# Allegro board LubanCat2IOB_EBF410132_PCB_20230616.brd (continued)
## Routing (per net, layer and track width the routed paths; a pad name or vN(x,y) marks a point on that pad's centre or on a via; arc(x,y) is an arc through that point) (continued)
MIPI_DSI_TX1_D0P: length 207.4
  TOP w0.124: v1(116.97,56.97) 117.27,57.27 130.78,57.27 133.78,54.28 150.55,54.28 150.64,54.19 J26.26 ; v1(19.89,66.73) 20.19,67.03 35.7,67.03 35.87,66.86 35.87,64.72 35.78,64.63 J3.15
  ART03 w0.113: v1(19.89,66.73) 20.21,67.05 20.43,67.05 20.62,66.86 20.62,48.34 21.03,47.94 21.4,47.94 arc(21.46,47.91) 21.48,47.86 arc(21.5,47.8) 21.56,47.77 21.85,47.77 arc(21.91,47.8) 21.93,47.86 arc(21.95,47.91) 22.01,47.94 22.3,47.94 arc(22.36,47.91) 22.38,47.86 arc(22.41,47.8) 22.46,47.77 22.75,47.77 arc(22.81,47.8) 22.83,47.86 arc(22.86,47.91) 22.91,47.94 23.2,47.94 arc(23.26,47.91) 23.28,47.86 arc(23.31,47.8) 23.36,47.77 23.65,47.77 arc(23.71,47.8) 23.73,47.86 arc(23.76,47.91) 23.82,47.94 32.68,47.94 32.97,48.23 32.97,49.64 33.11,49.77 33.29,49.77 33.42,49.64 33.42,48.28 33.77,47.94 34.22,47.94 34.51,48.23 34.51,49.64 34.64,49.77 34.83,49.77 34.96,49.64 34.96,48.28 35.3,47.94 35.75,47.94 36.04,48.23 36.04,49.64 36.17,49.77 36.36,49.77 36.49,49.64 36.49,48.28 36.84,47.94 37.28,47.94 37.58,48.23 37.58,49.64 37.71,49.77 37.9,49.77 38.03,49.64 38.03,48.28 38.37,47.94 38.82,47.94 39.11,48.23 39.11,49.64 39.24,49.77 39.43,49.77 39.56,49.64 39.56,48.28 39.9,47.94 40.35,47.94 40.64,48.23 40.64,49.64 40.78,49.77 40.96,49.77 41.1,49.64 41.1,48.28 41.44,47.94 41.89,47.94 42.18,48.23 42.18,49.64 42.31,49.77 42.5,49.77 42.63,49.64 42.63,48.28 42.97,47.94 43.42,47.94 45.99,45.37 92.43,45.37 93.1,44.7 108.41,44.7 108.71,45 108.71,50.29 108.99,50.57 110.5,50.57 110.79,50.87 110.79,57.02 111.05,57.28 116.66,57.28 v1(116.97,56.97)
MIPI_DSI_TX1_D1N: length 208.5
  TOP w0.124: v1(116.99,55.14) 117.25,54.88 129.68,54.88 132.95,51.61 150.55,51.61 150.64,51.69 J26.21 ; J3.21 37.28,64.63 37.2,64.72 37.2,67.91 36.36,68.75 16.71,68.75 v1(16.41,69.05)
  ART03 w0.113: v1(116.99,55.14) 116.69,54.84 115.15,54.84 114.81,54.49 114.81,53.32 115.13,53 116.24,53 116.37,52.87 116.37,52.69 116.24,52.55 115.13,52.55 114.81,52.24 114.81,51.79 115.13,51.47 116.24,51.47 116.37,51.34 116.37,51.15 116.24,51.02 115.13,51.02 114.81,50.7 114.81,50.25 115.13,49.94 116.24,49.94 116.37,49.8 116.37,49.62 116.24,49.48 115.13,49.48 114.81,49.17 114.81,48.72 115.13,48.4 116.24,48.4 116.37,48.27 116.37,48.08 116.24,47.95 115.13,47.95 114.81,47.63 114.81,47 114.59,46.78 111.77,46.78 111.35,46.37 111.35,43.05 110.98,42.68 90.94,42.68 90.17,43.45 44.64,43.45 42.75,45.34 17.86,45.34 17.66,45.53 17.66,68.38 17.3,68.74 16.72,68.74 v1(16.41,69.05)
MIPI_DSI_TX1_D1P: length 208.5
  TOP w0.124: v1(16.41,68.12) 16.71,68.42 36.22,68.42 36.87,67.77 36.87,64.72 36.78,64.63 J3.19 ; v1(116.99,54.22) 117.33,54.56 129.54,54.56 132.82,51.28 150.55,51.28 150.64,51.19 J26.20
  ART03 w0.113: v1(116.99,54.22) 116.69,54.52 115.28,54.52 115.12,54.36 115.12,53.45 115.26,53.32 116.37,53.32 116.69,53 116.69,52.55 116.37,52.24 115.26,52.24 115.12,52.1 115.12,51.92 115.26,51.79 116.37,51.79 116.69,51.47 116.69,51.02 116.37,50.7 115.26,50.7 115.12,50.57 115.12,50.38 115.26,50.25 116.37,50.25 116.69,49.93 116.69,49.49 116.37,49.17 115.26,49.17 115.12,49.04 115.12,48.85 115.26,48.72 116.37,48.72 116.69,48.4 116.69,47.95 116.37,47.63 115.26,47.63 115.12,47.5 115.12,46.87 114.72,46.47 114.09,46.47 arc(114.02,46.44) 114,46.37 arc(113.97,46.3) 113.9,46.27 113.64,46.27 arc(113.57,46.3) 113.54,46.37 arc(113.52,46.44) 113.45,46.47 113.19,46.47 arc(113.12,46.44) 113.09,46.37 arc(113.07,46.3) 113,46.27 112.74,46.27 arc(112.67,46.3) 112.64,46.37 arc(112.61,46.44) 112.55,46.47 111.9,46.47 111.67,46.24 111.67,42.92 111.11,42.36 90.8,42.36 90.04,43.13 44.51,43.13 42.62,45.02 17.72,45.02 17.35,45.4 17.35,68.25 17.17,68.42 16.71,68.42 v1(16.41,68.12)
MIPI_DSI_TX1_D2N: length 208.1
  TOP w0.124: J3.33 40.28,64.63 40.2,64.72 40.2,68.59 37.24,71.54 14.83,71.54 v1(14.5,71.87) ; J26.18 150.64,50.19 150.55,50.11 132.26,50.11 128.84,53.53 120.12,53.53 v1(119.86,53.79)
  ART03 w0.113: v1(14.5,71.87) 14.78,71.59 15.29,71.59 15.63,71.25 15.63,66.86 16.23,66.26 16.23,44.5 16.43,44.3 42.08,44.3 44.09,42.29 88.66,42.29 89.27,41.68 113.93,41.68 117.79,45.54 117.79,53.15 118.15,53.5 119.58,53.5 v1(119.86,53.79)
MIPI_DSI_TX1_D2P: length 208
  TOP w0.124: J26.17 150.64,49.69 150.55,49.78 132.13,49.78 128.7,53.2 120.17,53.2 v1(119.86,52.9) ; v1(14.5,70.94) 14.78,71.22 37.11,71.22 39.87,68.46 39.87,64.72 39.78,64.63 J3.31
  ART03 w0.113: v1(119.86,52.9) 119.58,53.18 118.28,53.18 118.11,53.02 118.11,52.62 arc(118.14,52.55) 118.21,52.52 arc(118.28,52.49) 118.31,52.42 118.31,52.17 arc(118.28,52.1) 118.21,52.07 arc(118.14,52.04) 118.11,51.97 118.11,51.72 arc(118.14,51.65) 118.21,51.62 arc(118.28,51.59) 118.31,51.52 118.31,51.27 arc(118.28,51.2) 118.21,51.17 arc(118.14,51.14) 118.11,51.07 118.11,45.41 114.06,41.37 89.14,41.37 88.53,41.98 43.96,41.98 41.95,43.98 16.3,43.98 15.91,44.37 15.91,66.13 15.32,66.73 15.32,71.12 15.16,71.27 14.83,71.27 v1(14.5,70.94)
MIPI_DSI_TX1_D3N: length 206.9
  TOP w0.124: v1(24.04,73.21) 24.36,72.89 37.87,72.89 41.2,69.57 41.2,64.72 41.28,64.63 J3.37 ; v1(117.86,60.83) 117.63,60.6 117.63,59.05 117.8,58.88 131.14,58.88 133.91,56.11 150.55,56.11 150.64,56.19 J26.30
  ART03 w0.113: v1(24.04,73.21) 23.8,72.96 22.41,72.96 22,72.55 22,51.49 22.4,51.09 30.72,51.09 31.04,51.41 31.04,52.02 31.17,52.16 31.36,52.16 31.49,52.02 31.49,51.41 31.8,51.09 32.25,51.09 32.57,51.41 32.57,52.02 32.7,52.16 32.89,52.16 33.02,52.02 33.02,51.41 33.34,51.09 33.79,51.09 34.1,51.41 34.1,52.02 34.24,52.16 34.42,52.16 34.56,52.02 34.56,51.41 34.87,51.09 35.32,51.09 35.64,51.41 35.64,52.02 35.77,52.16 35.96,52.16 36.09,52.02 36.09,51.41 36.41,51.09 36.86,51.09 37.17,51.41 37.17,52.02 37.31,52.16 37.49,52.16 37.62,52.02 37.62,51.41 37.94,51.09 38.39,51.09 38.71,51.41 38.71,52.02 38.84,52.16 39.03,52.16 39.16,52.02 39.16,51.41 39.48,51.09 45.17,51.09 45.4,50.86 45.4,48.07 46.82,46.66 97.65,46.66 98.18,47.19 98.18,50.77 98.47,51.05 102.08,51.05 102.79,51.76 102.79,58.17 103.31,58.68 117.13,58.68 117.57,59.12 117.57,60.54 v1(117.86,60.83)
MIPI_DSI_TX1_D3P: length 206.9
  TOP w0.124: v1(24.04,72.28) 24.33,72.56 37.74,72.56 40.87,69.43 40.87,64.72 40.78,64.63 J3.35 ; v1(116.97,60.83) 117.3,60.49 117.3,58.92 117.66,58.55 131,58.55 133.78,55.78 150.55,55.78 150.64,55.69 J26.29
  ART03 w0.113: v1(116.97,60.83) 117.25,60.54 117.25,59.25 117,59 103.17,59 102.48,58.3 102.48,51.89 101.95,51.37 98.33,51.37 97.87,50.9 97.87,47.32 97.52,46.97 46.95,46.97 45.72,48.21 45.72,50.99 45.3,51.41 39.61,51.41 39.47,51.54 39.47,52.16 39.16,52.47 38.71,52.47 38.39,52.16 38.39,51.54 38.26,51.41 38.07,51.41 37.94,51.54 37.94,52.16 37.62,52.47 37.17,52.47 36.86,52.16 36.86,51.54 36.73,51.41 36.54,51.41 36.41,51.54 36.41,52.16 36.09,52.47 35.64,52.47 35.32,52.16 35.32,51.54 35.19,51.41 35,51.41 34.87,51.54 34.87,52.16 34.55,52.47 34.11,52.47 33.79,52.16 33.79,51.54 33.66,51.41 33.47,51.41 33.34,51.54 33.34,52.16 33.02,52.47 32.57,52.47 32.25,52.16 32.25,51.54 32.12,51.41 31.94,51.41 31.8,51.54 31.8,52.16 31.49,52.47 31.04,52.47 30.72,52.16 30.72,51.54 30.59,51.41 28.71,51.41 arc(28.65,51.43) 28.62,51.49 arc(28.6,51.56) 28.54,51.58 28.26,51.58 arc(28.2,51.56) 28.17,51.49 arc(28.15,51.43) 28.08,51.41 27.84,51.41 arc(27.76,51.44) 27.73,51.52 arc(27.7,51.6) 27.62,51.63 27.39,51.63 arc(27.31,51.6) 27.28,51.52 arc(27.25,51.44) 27.16,51.41 26.94,51.41 arc(26.86,51.44) 26.83,51.52 arc(26.79,51.6) 26.71,51.63 26.49,51.63 arc(26.41,51.6) 26.38,51.52 arc(26.34,51.44) 26.26,51.41 26.04,51.41 arc(25.96,51.44) 25.93,51.52 arc(25.89,51.6) 25.81,51.63 25.59,51.63 arc(25.51,51.6) 25.47,51.52 arc(25.44,51.44) 25.36,51.41 25.14,51.41 arc(25.06,51.44) 25.02,51.52 arc(24.99,51.6) 24.91,51.63 24.69,51.63 arc(24.61,51.6) 24.57,51.52 arc(24.54,51.44) 24.46,51.41 24.22,51.41 arc(24.15,51.44) 24.12,51.51 arc(24.09,51.58) 24.02,51.61 23.77,51.61 arc(23.7,51.58) 23.67,51.51 arc(23.64,51.44) 23.56,51.41 22.53,51.41 22.31,51.62 22.31,72.42 22.54,72.65 23.8,72.65 24.04,72.41 v1(24.04,72.28)
OE: length 4.4
  TOP w0.156: U21.8 142.43,74.62 142.61,74.45 142.61,72.73 R83.2
ON/OFF_KEY: length 54.5
  TOP w0.156: J1.25 38.28,24.25 38.13,24.41 34.52,24.41 v1(34.04,24.89)
  ART03 w0.142: v1(12.79,23.17) 12.79,19.53 13.08,19.25 33.75,19.25 34.04,19.53 34.04,22.78 33.56,23.26 33.56,24.41 v1(34.04,24.89)
  BOTTOM w0.156: v1(12.79,23.17) C64.1 12.73,22.53 12.73,20.21 D2.2 12.95,18.71 12.95,11.56 13.27,11.25 15.26,11.25 SW2.2
PCIE20_CLKREQN_M1: length 89.5
  TOP w0.156: J4.37 v1(66.28,64.94)
  ART03 w0.142: v1(66.28,64.94) 66.28,53.85 66.57,53.56 92.65,53.56 92.94,53.85 92.94,55.88 94.16,57.1 96.81,57.1 96.95,57.24 96.95,63.62 97.63,64.3 107.97,64.3 108.39,64.72 108.39,71.43 108.92,71.95 124.86,71.95 v1(125.48,72.57)
  BOTTOM w0.156: R30.1 v1(125.48,72.57)
PCIE20_PERSTN_M1: length 60.5
  TOP w0.156: v1(95.09,60.75) 95.6,61.26 97.12,61.26 97.43,61.57 97.43,62.89 97.82,63.27 116.56,63.27 116.97,63.67 R63.2 ; J4.59 v1(71.78,61.94)
  ART03 w0.142: v1(95.09,60.75) 95.57,60.28 95.57,59.23 95.11,58.77 89.67,58.77 89.38,58.49 89.38,56.06 89.1,55.77 72.55,55.77 72.26,56.06 72.26,61.46 v1(71.78,61.94)
PCIE20_REFCLKN: length 142.6
  TOP w0.179: J35.11 124.7,75.42 124.49,75.22 124.49,73.45 124.03,73 117.81,73 v1(117.5,72.69) ; J1.54 45.28,27.72 45.22,27.78 45.22,40.98 49.28,45.03 98.69,45.03 99.14,45.49 99.14,46.1 v1(99.44,46.4)
  BOTTOM w0.179: v1(99.44,46.4) 99.14,46.1 99.14,45.44 98.6,44.9 97.33,44.9 96.7,45.54 96.7,60.25 99.8,63.35 99.8,76.53 100.5,77.24 114.45,77.24 115.47,76.22 118.57,76.22 119.1,75.69 119.1,73.42 118.62,72.94 117.75,72.94 v1(117.5,72.69)
PCIE20_REFCLKP: length 142.6
  TOP w0.179: J35.13 123.9,75.42 124.11,75.22 124.11,73.61 123.88,73.38 117.8,73.38 v1(117.5,73.68) ; J1.52 44.78,27.72 44.84,27.78 44.84,41.14 49.12,45.42 98.53,45.42 98.76,45.64 98.76,46.1 v1(98.46,46.4)
  BOTTOM w0.179: v1(98.46,46.4) 98.76,46.1 98.76,45.6 98.44,45.29 97.49,45.29 97.08,45.7 97.08,60.09 100.18,63.19 100.18,71.87 arc(100.23,71.99) 100.36,72.04 arc(100.48,72.1) 100.53,72.22 100.53,72.58 arc(100.48,72.71) 100.36,72.76 arc(100.23,72.81) 100.18,72.94 100.18,73.3 arc(100.23,73.42) 100.36,73.47 arc(100.48,73.53) 100.53,73.65 100.53,74.01 arc(100.48,74.14) 100.36,74.19 arc(100.23,74.24) 100.18,74.37 100.18,74.72 arc(100.23,74.85) 100.36,74.9 arc(100.48,74.95) 100.53,75.08 100.53,75.44 arc(100.48,75.56) 100.36,75.62 arc(100.23,75.67) 100.18,75.79 100.18,76.37 100.66,76.86 101.38,76.86 arc(101.49,76.81) 101.54,76.69 101.54,76.67 arc(101.59,76.55) 101.71,76.5 102.09,76.5 arc(102.21,76.55) 102.26,76.67 102.26,76.69 arc(102.3,76.81) 102.42,76.86 102.81,76.86 arc(102.92,76.81) 102.97,76.69 102.97,76.67 arc(103.02,76.55) 103.14,76.5 103.52,76.5 arc(103.64,76.55) 103.69,76.67 103.69,76.69 arc(103.73,76.81) 103.85,76.86 104.23,76.86 arc(104.35,76.81) 104.4,76.69 104.4,76.67 arc(104.45,76.55) 104.56,76.5 104.95,76.5 arc(105.07,76.55) 105.11,76.67 105.11,76.69 arc(105.16,76.81) 105.28,76.86 105.66,76.86 arc(105.78,76.81) 105.83,76.69 105.83,76.67 arc(105.88,76.55) 105.99,76.5 106.38,76.5 arc(106.49,76.55) 106.54,76.67 106.54,76.69 arc(106.59,76.81) 106.71,76.86 107.09,76.86 arc(107.21,76.81) 107.26,76.69 107.26,76.67 arc(107.3,76.55) 107.42,76.5 107.81,76.5 arc(107.92,76.55) 107.97,76.67 107.97,76.69 arc(108.02,76.81) 108.14,76.86 111.97,76.86 arc(112.08,76.81) 112.13,76.69 arc(112.18,76.57) 112.29,76.53 112.68,76.53 arc(112.8,76.57) 112.84,76.69 arc(112.89,76.81) 113.01,76.86 114.29,76.86 115.31,75.84 118.42,75.84 118.72,75.54 118.72,73.58 118.47,73.33 117.85,73.33 v1(117.5,73.68)
PCIE20_RXN: length 148.5
  TOP w0.179: v1(100.2,47.34) 99.9,47.65 98.32,47.65 96.97,46.3 48.24,46.3 43.72,41.78 43.72,27.78 43.78,27.72 J1.48 ; v1(105.84,72.49) 106.12,72.21 106.12,71.34 106.55,70.91 108.81,70.91 109.35,71.45 115.93,71.45 116.49,72.01 116.49,75.22 116.7,75.42 J35.23
  BOTTOM w0.179: v1(105.84,72.49) 106.15,72.19 106.15,71.27 105.94,71.07 101.55,71.07 101.07,70.58 101.07,61.73 100.86,61.52 99.67,61.52 99.24,61.09 99.24,60.48 99.67,60.05 101.09,60.05 101.3,59.84 101.3,59.52 101.06,59.28 98.2,59.28 97.76,58.85 97.76,58.24 98.17,57.83 101.21,57.83 101.4,57.64 101.4,57.35 101.16,57.11 98.22,57.11 97.76,56.66 97.76,56.04 98.17,55.64 101.21,55.64 101.4,55.45 101.4,55.16 101.16,54.92 98.22,54.92 97.76,54.46 97.76,53.85 98.17,53.44 100.98,53.44 101.17,53.26 101.17,52.96 100.91,52.7 98.37,52.7 97.79,52.12 97.79,48.07 98.22,47.65 99.9,47.65 v1(100.2,47.34)
PCIE20_RXP: length 148.1
  TOP w0.179: J35.25 115.9,75.42 116.11,75.22 116.11,72.16 115.77,71.83 109.2,71.83 108.65,71.29 106.71,71.29 106.5,71.5 106.5,72.16 v1(106.83,72.49) ; J1.46 43.28,27.72 43.34,27.78 43.34,41.94 48.08,46.68 96.81,46.68 98.17,48.03 99.9,48.03 v1(100.2,48.33)
  BOTTOM w0.179: v1(100.2,48.33) 99.9,48.03 98.37,48.03 98.17,48.23 98.17,51.96 98.53,52.32 101.07,52.32 101.55,52.8 101.55,53.42 101.14,53.83 98.33,53.83 98.15,54.01 98.15,54.31 98.38,54.54 101.32,54.54 101.78,55 101.78,55.61 101.37,56.02 98.33,56.02 98.15,56.2 98.15,56.5 98.38,56.73 101.32,56.73 101.78,57.19 101.78,57.8 101.37,58.21 98.33,58.21 98.15,58.39 98.15,58.69 98.36,58.9 101.22,58.9 101.68,59.36 101.68,59.99 101.24,60.43 99.83,60.43 99.62,60.64 99.62,60.93 99.83,61.14 101.02,61.14 101.45,61.57 101.45,70.42 101.71,70.68 102.04,70.68 arc(102.13,70.65) 102.17,70.56 arc(102.2,70.47) 102.29,70.43 102.75,70.43 arc(102.84,70.47) 102.88,70.56 arc(102.92,70.65) 103.01,70.68 103.47,70.68 arc(103.56,70.65) 103.6,70.56 arc(103.63,70.47) 103.72,70.43 104.18,70.43 arc(104.27,70.47) 104.31,70.56 arc(104.35,70.65) 104.44,70.68 104.9,70.68 arc(104.99,70.65) 105.02,70.56 arc(105.06,70.47) 105.15,70.43 105.61,70.43 arc(105.7,70.47) 105.74,70.56 arc(105.78,70.65) 105.87,70.68 106.1,70.68 106.53,71.11 106.53,72.19 v1(106.83,72.49)
PCIE20_TXN: length 137.8
  TOP w0.179: J1.44 42.78,27.72 42.75,27.75 42.75,43.38 46.97,47.6 96.52,47.6 98.04,49.12 99.92,49.12 100.36,49.55 100.36,49.95 100.38,49.97 100.38,49.99 v1(100.66,50.26)
  BOTTOM w0.179: C53.1 113.27,71.46 113.27,69.24 112.76,68.73 102.95,68.73 102.59,68.37 102.59,65.52 102.8,65.31 104.47,65.31 104.88,64.91 104.88,64.26 104.47,63.86 103.16,63.86 102.92,63.62 102.92,63.33 103.1,63.14 105.28,63.14 105.69,62.74 105.69,62.12 105.23,61.67 103.16,61.67 102.92,61.43 102.92,61.13 103.1,60.95 105.28,60.95 105.69,60.54 105.69,59.93 105.23,59.47 103.16,59.47 102.92,59.24 102.92,58.94 103.1,58.76 105.28,58.76 105.69,58.35 105.69,57.74 105.23,57.28 103.16,57.28 102.92,57.05 102.92,56.75 103.1,56.57 104.85,56.57 105.28,56.13 105.28,55.52 104.85,55.09 103.16,55.09 102.92,54.85 102.92,54.56 103.1,54.37 104.85,54.37 105.28,53.94 105.28,53.33 104.85,52.9 102.83,52.9 102.59,52.66 102.59,51.83 102.09,51.33 100.62,51.33 100.35,51.07 100.35,50.56 v1(100.66,50.26)
PCIE20_TXP: length 137.8
  TOP w0.179: v1(99.67,50.26) 99.97,49.96 99.97,49.71 99.77,49.5 97.89,49.5 96.36,47.98 46.81,47.98 42.37,43.54 42.37,27.65 42.28,27.56 J1.42
  BOTTOM w0.179: C54.1 112.89,71.46 112.89,69.4 112.6,69.11 102.79,69.11 102.21,68.52 102.21,65.36 102.64,64.93 104.32,64.93 104.49,64.75 104.49,64.42 104.32,64.24 103,64.24 102.54,63.78 102.54,63.17 102.95,62.76 105.12,62.76 105.31,62.58 105.31,62.28 105.07,62.05 103,62.05 102.54,61.59 102.54,60.98 102.95,60.57 105.12,60.57 105.31,60.39 105.31,60.09 105.07,59.85 103,59.85 102.54,59.4 102.54,58.78 102.95,58.38 105.12,58.38 105.31,58.19 105.31,57.9 105.07,57.66 103,57.66 102.54,57.2 102.54,56.59 102.95,56.19 104.69,56.19 104.9,55.98 104.9,55.68 104.69,55.47 103,55.47 102.54,55.01 102.54,54.4 102.95,53.99 104.69,53.99 104.9,53.78 104.9,53.49 104.69,53.28 102.67,53.28 102.21,52.82 102.21,51.99 101.93,51.71 100.46,51.71 99.97,51.23 99.97,50.56 v1(99.67,50.26)
PCIE20_WAKEN_M1: length 94.4
  TOP w0.156: v1(66.28,65.94) 66.78,65.44 J4.39
  ART03 w0.142: v1(125.48,71.57) 125.38,71.47 109.12,71.47 108.81,71.17 108.81,64.33 108.36,63.88 97.97,63.88 97.38,63.29 97.38,56.72 97.24,56.57 94.25,56.57 93.4,55.72 93.4,53.41 93.12,53.14 66.09,53.14 65.81,53.42 65.81,65.46 v1(66.28,65.94)
  BOTTOM w0.156: v1(125.48,71.57) 125.91,72.01 126.81,72.01 R29.1
PCIE30_REFCLKN_IN: length 183.3
  TOP w0.179: R78.2 145.03,82.42 145.35,82.73 145.35,83.02 v1(145.08,83.29) ; J1.71 v1(49.78,23.89)
  ART03 w0.163: v1(137.91,47.34) 137.91,47.43 137.7,47.64 137.08,47.64 136.92,47.47 136.92,46.83 137.16,46.59 138.96,46.59 139.41,46.15 139.41,45.55 139,45.15 137.72,45.15 137.53,44.96 137.53,44.69 137.72,44.5 139,44.5 139.41,44.09 139.41,43.52 139,43.11 137.72,43.11 137.53,42.92 137.53,42.65 137.72,42.46 139,42.46 139.41,42.06 139.41,41.49 139,41.08 137.72,41.08 137.53,40.89 137.53,40.59 137.69,40.43 139,40.43 139.41,40.02 139.41,39.39 138.96,38.95 135.25,38.95 135.09,38.79 135.09,37.53 134.69,37.13 134.11,37.13 133.71,37.53 133.71,38.79 133.54,38.95 132.82,38.95 132.64,38.77 132.64,36.52 130.81,34.69 130.81,30.59 130.31,30.1 69.24,30.1 66.43,32.9 51.53,32.9 50.21,31.58 50.21,25.48 50.27,25.42 50.27,24.69 49.78,24.2 v1(49.78,23.89)
  ART04 w0.163: v1(137.91,47.34) 137.64,47.6 136.95,47.6 136.55,48 136.55,51.21 137.04,51.7 146.89,51.7 147.21,52.01 147.21,81.41 147.05,81.57 145.85,81.57 145.36,82.06 145.36,83.01 v1(145.08,83.29)
  BOTTOM w0.179: R78.2 145.36,82.28 145.36,83.01 v1(145.08,83.29)
PCIE30_REFCLKP_IN: length 184
  TOP w0.179: J1.69 49.28,24.39 v1(49.78,24.89) ; R77.2 146.05,82.42 145.73,82.73 145.73,83.02 v1(146.01,83.29)
  ART03 w0.163: v1(137.91,48.31) 137.6,48 136.93,48 136.55,47.62 136.55,46.68 137.01,46.22 138.81,46.22 139.04,46 139.04,45.71 138.85,45.52 137.57,45.52 137.16,45.11 137.16,44.54 137.57,44.13 138.85,44.13 139.04,43.94 139.04,43.67 138.85,43.48 137.57,43.48 137.16,43.08 137.16,42.5 137.57,42.1 138.85,42.1 139.04,41.91 139.04,41.64 138.85,41.45 137.57,41.45 137.16,41.04 137.16,40.44 137.54,40.06 138.85,40.06 139.04,39.87 139.04,39.54 138.81,39.32 135.1,39.32 134.72,38.94 134.72,37.69 134.53,37.5 134.26,37.5 134.07,37.69 134.07,38.94 133.69,39.32 132.66,39.32 132.27,38.92 132.27,36.67 130.44,34.84 130.44,30.75 130.16,30.46 69.39,30.46 66.58,33.27 51.38,33.27 49.84,31.73 49.84,25.51 49.78,25.45 v1(49.78,24.89)
  ART04 w0.163: v1(146.01,83.29) 145.73,83.01 145.73,82.21 146,81.94 147.2,81.94 147.57,81.56 147.57,51.86 147.04,51.33 140.18,51.33 arc(140.07,51.29) 140.03,51.18 arc(139.98,51.07) 139.87,51.02 139.53,51.02 arc(139.42,51.07) 139.37,51.18 arc(139.33,51.29) 139.22,51.33 138.88,51.33 arc(138.77,51.29) 138.72,51.18 arc(138.68,51.07) 138.57,51.02 138.23,51.02 arc(138.12,51.07) 138.07,51.18 arc(138.03,51.29) 137.92,51.33 137.19,51.33 136.92,51.06 136.92,48.15 137.1,47.97 137.57,47.97 v1(137.91,48.31)
  BOTTOM w0.179: v1(146.01,83.29) 145.75,83.03 145.75,82.26 R77.2
PCIE30_RX0N: length 186.1
  TOP w0.179: v1(146.46,94.29) 146.71,94.04 146.71,93.14 146.65,93.08 J17.41 ; J1.61 47.28,24.39 v1(46.78,24.89)
  ART03 w0.163: v1(46.78,24.89) 46.78,25.44 46.84,25.51 46.84,32.07 50.26,35.48 67.82,35.48 70.46,32.85 126.88,32.85 127.12,33.08 127.12,37.32 127.53,37.74 128.58,37.74 v1(128.88,38.04)
  ART04 w0.163: v1(128.88,38.04) 129.18,37.74 133.19,37.74 133.44,37.99 133.44,40.76 133.92,41.25 147.72,41.25 147.89,41.42 147.89,46.2 148.36,46.67 151.6,46.67 151.83,46.9 151.83,82.64 152.97,83.78 152.97,90.91 152.65,91.24 147.86,91.24 146.72,92.38 146.72,94.03 v1(146.46,94.29)
PCIE30_RX0P: length 186.1
  TOP w0.179: J17.43 147.15,93.08 147.09,93.14 147.09,94.04 v1(147.34,94.29) ; J1.59 v1(46.78,23.89)
  ART03 w0.163: v1(128.88,37.07) 128.58,37.37 127.69,37.37 127.48,37.17 127.48,32.93 127.04,32.48 70.31,32.48 67.67,35.12 50.41,35.12 47.21,31.92 47.21,25.51 47.27,25.44 47.27,24.66 46.78,24.17 v1(46.78,23.89)
  ART04 w0.163: v1(147.34,94.29) 147.08,94.03 147.08,92.53 148.01,91.61 152.8,91.61 153.34,91.06 153.34,83.63 152.2,82.49 152.2,46.75 151.75,46.3 148.51,46.3 148.26,46.05 148.26,41.27 147.87,40.88 134.08,40.88 133.81,40.61 133.81,37.84 133.34,37.37 129.18,37.37 v1(128.88,37.07)
PCIE30_RX1N: length 186.1
  TOP w0.179: J1.65 48.28,24.39 v1(47.78,24.89) ; v1(143.46,94.29) 143.71,94.04 143.71,93.14 143.65,93.08 J17.29
  ART03 w0.163: v1(130.25,39.64) 130.56,39.34 130.56,37.06 129.04,35.55 129.04,32.27 128.71,31.93 69.9,31.93 67.17,34.67 50.8,34.67 47.84,31.71 47.84,25.54 47.78,25.48 47.78,24.89 v1(47.78,24.89)
  ART04 w0.163: v1(143.46,94.29) 143.72,94.03 143.72,88.76 144.15,88.33 150.43,88.33 150.87,87.89 150.87,48.93 150.57,48.64 146.07,48.64 145.64,48.22 145.64,43.15 145.34,42.85 144.22,42.85 144.03,43.04 144.03,43.53 143.63,43.94 143.05,43.94 142.65,43.53 142.65,43.04 142.46,42.85 131.08,42.85 130.59,42.36 130.59,39.98 v1(130.25,39.64)
PCIE30_RX1P: length 186.1
  TOP w0.179: v1(144.34,94.29) 144.09,94.04 144.09,93.14 144.15,93.08 J17.31 ; J1.63 v1(47.78,23.89)
  ART03 w0.163: v1(47.78,23.89) 47.78,24.16 48.27,24.65 48.27,25.46 48.21,25.52 48.21,31.56 50.95,34.3 67.01,34.3 69.75,31.57 128.86,31.57 129.41,32.12 129.41,35.4 130.92,36.91 130.92,39.34 v1(131.22,39.64)
  ART04 w0.163: v1(144.34,94.29) 144.08,94.03 144.08,88.91 144.3,88.69 150.58,88.69 151.23,88.04 151.23,48.78 150.72,48.27 146.22,48.27 146.01,48.06 146.01,43 145.49,42.48 144.07,42.48 143.67,42.89 143.67,43.38 143.48,43.57 143.21,43.57 143.01,43.38 143.01,42.89 142.61,42.48 131.23,42.48 130.96,42.21 130.96,39.91 v1(131.22,39.64)
PCIE30_TX0N: length 182.5
  TOP w0.179: J1.53 45.28,24.39 v1(44.78,24.89)
  ART03 w0.163: v1(128.26,41.62) 127.96,41.32 124.83,41.32 124.33,40.82 124.33,34.95 124.05,34.67 71.4,34.67 68.9,37.17 49.13,37.17 44.85,32.89 44.85,25.41 44.78,25.34 v1(44.78,24.89)
  ART04 w0.163: v1(128.26,41.62) 128.56,41.32 128.87,41.32 129.05,41.5 129.05,43.45 129.57,43.96 139.01,43.96 139.38,44.33 139.38,49.63 139.85,50.1 140.83,50.1 141.24,49.69 141.24,48.38 141.43,48.19 141.7,48.19 141.89,48.38 141.89,49.69 142.29,50.1 142.87,50.1 143.27,49.69 143.27,48.38 143.46,48.19 143.73,48.19 143.92,48.38 143.92,49.69 144.33,50.1 147.86,50.1 148.15,50.38 148.15,51.13 148.55,51.54 149.51,51.54 149.7,51.73 149.7,52 149.51,52.19 148.55,52.19 148.15,52.59 148.15,53.17 148.55,53.57 149.51,53.57 149.7,53.76 149.7,54.03 149.51,54.22 148.55,54.22 148.15,54.63 148.15,55.2 148.55,55.6 149.51,55.6 149.7,55.8 149.7,56.07 149.51,56.26 148.55,56.26 148.15,56.66 148.15,86.53 v1(147.89,86.78)
  BOTTOM w0.179: C125.1 148.11,87.66 148.11,86.99 v1(147.89,86.78)
PCIE30_TX0P: length 182.6
  TOP w0.179: J1.51 v1(44.78,23.89)
  ART03 w0.163: v1(44.78,23.89) 44.78,24.2 45.28,24.69 45.28,25.35 45.22,25.41 45.22,32.74 49.28,36.8 68.75,36.8 71.25,34.3 124.21,34.3 124.7,34.79 124.7,40.67 124.98,40.96 127.96,40.96 v1(128.26,40.65)
  ART04 w0.163: v1(148.78,86.78) 148.51,86.52 148.51,56.81 148.7,56.62 149.66,56.62 150.06,56.22 150.06,55.64 149.66,55.24 148.7,55.24 148.51,55.05 148.51,54.78 148.7,54.59 149.66,54.59 150.06,54.18 150.06,53.61 149.66,53.2 148.7,53.2 148.51,53.01 148.51,52.74 148.7,52.55 149.66,52.55 150.06,52.15 150.06,51.57 149.66,51.17 148.7,51.17 148.51,50.98 148.51,50.23 148.02,49.73 144.48,49.73 144.29,49.54 144.29,48.23 143.88,47.82 143.31,47.82 142.91,48.23 142.91,49.54 142.72,49.73 142.45,49.73 142.25,49.54 142.25,48.23 141.85,47.82 141.28,47.82 140.87,48.23 140.87,49.54 140.68,49.73 140,49.73 139.75,49.48 139.75,44.18 139.17,43.6 129.72,43.6 129.41,43.29 129.41,41.35 129.02,40.96 128.56,40.96 v1(128.26,40.65)
  BOTTOM w0.179: C126.1 148.49,87.58 148.49,87.07 v1(148.78,86.78)
PCIE30_TX1N: length 182.6
  TOP w0.179: J1.57 46.28,24.39 v1(45.78,24.89)
  ART03 w0.163: v1(125.65,39.67) 125.96,39.36 125.96,34.08 125.69,33.81 70.94,33.81 68.4,36.35 49.76,36.35 45.84,32.43 45.84,25.51 45.78,25.46 v1(45.78,24.89)
  ART04 w0.163: v1(144.97,86.78) 145.25,86.5 145.25,85.56 145.03,85.34 142.13,85.34 141.65,84.86 141.65,81.25 142.06,80.83 144.88,80.83 145.16,80.56 145.16,76.12 144.92,75.88 143.8,75.88 143.3,75.37 143.3,71.63 143.71,71.21 145.27,71.21 145.43,71.04 145.43,53.4 145.12,53.09 133.6,53.09 133.06,52.55 133.06,51.23 133.47,50.83 134.19,50.83 134.38,50.64 134.38,50.37 134.19,50.17 133.47,50.17 133.06,49.77 133.06,49.2 133.47,48.79 134.19,48.79 134.38,48.6 134.38,48.33 134.19,48.14 133.47,48.14 133.06,47.73 133.06,45.45 132.79,45.18 126.48,45.18 125.95,44.65 125.95,43.9 126.35,43.5 127.64,43.5 127.8,43.33 127.8,43.01 127.64,42.84 126.35,42.84 125.95,42.44 125.95,39.97 v1(125.65,39.67)
  BOTTOM w0.179: v1(144.97,86.78) 145.26,87.07 145.26,87.58 C123.1
PCIE30_TX1P: length 182.8
  TOP w0.179: J1.55 v1(45.78,23.89)
  ART03 w0.163: v1(126.62,39.67) 126.32,39.38 126.32,33.93 125.84,33.45 70.79,33.45 68.25,35.99 49.91,35.99 46.2,32.28 46.2,25.5 46.27,25.43 46.27,24.63 45.78,24.14 v1(45.78,23.89)
  ART04 w0.163: v1(145.86,86.78) 145.62,86.54 145.62,85.41 145.19,84.97 142.28,84.97 142.01,84.71 142.01,81.4 142.21,81.2 145.03,81.2 145.53,80.71 145.53,75.97 145.07,75.51 143.95,75.51 143.66,75.22 143.66,71.78 143.87,71.57 145.42,71.57 145.8,71.2 145.8,53.25 145.27,52.73 133.76,52.73 133.43,52.4 133.43,51.38 133.62,51.19 134.34,51.19 134.75,50.79 134.75,50.21 134.34,49.81 133.62,49.81 133.43,49.62 133.43,49.35 133.62,49.16 134.34,49.16 134.75,48.75 134.75,48.18 134.34,47.77 133.62,47.77 133.43,47.58 133.43,45.3 132.94,44.82 126.63,44.82 126.31,44.5 126.31,44.05 126.5,43.86 127.79,43.86 128.17,43.48 128.17,42.86 127.79,42.48 126.5,42.48 126.31,42.29 126.31,41.35 arc(126.36,41.25) 126.45,41.21 arc(126.55,41.17) 126.59,41.07 126.59,40.7 arc(126.55,40.6) 126.45,40.56 arc(126.36,40.52) 126.31,40.42 126.31,39.97 v1(126.62,39.67)
  BOTTOM w0.179: v1(145.86,86.78) 145.64,86.99 145.64,87.66 C124.1
PCIE30X2_CLKREQN_M1: length 201.9
  TOP w0.156: v1(57.05,8.48) 57.05,17.85 54.23,20.67 54.23,23.95 53.85,24.33 51.16,24.33 50.78,23.96 J1.75 ; J17.52 149.4,86.21 149.27,86.34 149.27,87.91 148.77,88.41 138.68,88.41 135.44,85.18 135.44,81.62 133.41,79.59 133.41,72.68 v1(132.45,71.72)
  BOTTOM w0.156: v1(57.05,8.48) 75.31,8.48 77.34,10.51 115.33,10.51 115.65,10.82 115.65,21.1 116.79,22.24 116.79,28.27 114.55,30.5 114.55,37.07 114.24,37.38 110.85,37.38 110.54,37.7 110.54,62.45 110.85,62.76 117.63,62.76 118.19,63.32 118.19,69.03 118.5,69.34 132.13,69.34 132.45,69.65 v1(132.45,71.72)
PCIE30X2_PERSTN_M1: length 197.4
  TOP w0.156: J17.50 148.9,85.87 148.67,86.1 147.6,86.1 147.36,86.35 147.36,87.13 146.81,87.68 138.74,87.68 135.97,84.9 135.97,81.4 133.94,79.38 133.94,72.21 v1(133.45,71.72) ; J1.79 51.78,21.26 51.99,21.05 53.26,21.05 53.47,20.85 53.47,19.85 56.01,17.31 56.01,9.43 v1(55.05,8.48)
  BOTTOM w0.156: v1(133.45,71.72) 132.96,71.24 132.96,69.2 132.77,69.01 118.83,69.01 118.52,68.7 118.52,62.96 117.91,62.35 111.3,62.35 111.07,62.12 111.07,38.21 111.37,37.92 114.62,37.92 114.94,37.61 114.94,30.87 117.22,28.59 117.22,22.06 116.07,20.92 116.07,10.47 115.76,10.15 91.21,10.15 89.03,7.97 55.56,7.97 v1(55.05,8.48)
PCIE30X2_WAKEN_M1: length 204.9
  TOP w0.156: J1.77 51.28,23.75 51.54,24 53.57,24 53.82,23.75 53.82,20.21 56.54,17.49 56.54,8.97 v1(56.05,8.48) ; J17.54 149.9,85.79 150.32,86.2 150.32,88.46 149.76,89.02 136.4,89.02 134.92,87.55 134.92,81.83 132.89,79.8 132.89,73.17 v1(132.45,72.72)
  BOTTOM w0.156: v1(56.05,8.48) 56.54,8.96 74.9,8.96 76.86,10.92 114.83,10.92 115.14,11.23 115.14,21.31 116.38,22.55 116.38,27.94 114.12,30.2 114.12,36.55 113.77,36.9 110.37,36.9 110.06,37.22 110.06,62.88 110.37,63.19 117.33,63.19 117.83,63.7 117.83,69.46 118.14,69.77 131.61,69.77 131.93,70.08 131.93,72.2 v1(132.45,72.72)
PDN: length 6.2
  TOP w0.156: v1(142.47,71.67) 143.08,72.29 143.08,74.89 142.7,75.27 U21.7
  BOTTOM w0.156: R84.2 v1(142.47,71.67)
PE_TXN: length 4.7
  TOP w0.179: J35.31 113.5,75.42 113.29,75.22 113.29,73.62 v1(113.53,73.37)
  BOTTOM w0.179: C53.2 113.28,72.64 113.28,73.12 v1(113.53,73.37)
PE_TXP: length 4.7
  TOP w0.179: v1(112.64,73.37) 112.91,73.64 112.91,75.22 112.7,75.42 J35.33
  BOTTOM w0.179: C54.2 112.9,72.65 112.9,73.12 v1(112.64,73.37)
PETN0: length 3.4
  TOP w0.179: v1(147.96,89.83) 148.21,90.08 148.21,90.91 148.15,90.97 J17.47
  BOTTOM w0.179: v1(147.96,89.83) 148.16,89.63 148.16,89.27 C125.2
PETN1: length 3.5
  TOP w0.179: v1(144.96,89.83) 145.21,90.08 145.21,90.91 145.15,90.97 J17.35
  BOTTOM w0.179: C123.2 145.22,89.26 145.22,89.56 v1(144.96,89.83)
PETP0: length 3.5
  TOP w0.179: v1(148.84,89.83) 148.59,90.08 148.59,90.91 148.65,90.97 J17.49
  BOTTOM w0.179: C126.2 148.54,89.24 148.54,89.53 v1(148.84,89.83)
PETP1: length 3.4
  TOP w0.179: J17.37 145.65,90.97 145.59,90.91 145.59,90.08 v1(145.84,89.83)
  BOTTOM w0.179: v1(145.84,89.83) 145.61,89.59 145.61,89.26 C124.2
PHY0_CLKOUT125: length 2.5
  TOP w0.156: R105.2 75.67,76.3 U18.35
PHY0_LED1: length 41.4
  TOP w0.156: U18.33 74.38,75.5 v1(75.13,74.76) 75.79,74.09 R108.1
  TOP w0.203: J11.14 63.04,95.94 64.92,94.05 71.96,94.05 72.42,93.6 72.42,89.2 77.6,84.02 v1(77.6,82.67)
  BOTTOM w0.203: v1(75.13,74.76) 75.29,74.6 78.94,74.6 79.2,74.85 79.2,83.18 78.99,83.38 77.83,83.38 77.6,83.16 v1(77.6,82.67)
PHY0_LED2: length 29.1
  TOP w0.156: R109.1 75.78,75.1 v1(75.13,75.76) 74.98,75.9 U18.34
  TOP w0.203: v1(78.6,82.67) 78.6,83.73 72.95,89.38 72.95,95.2 J11.12
  BOTTOM w0.203: v1(78.6,82.67) 78.6,76.02 78.19,75.61 75.27,75.61 v1(75.13,75.76)
PHY1_CLKOUT125: length 2.5
  TOP w0.156: U19.35 94.85,76.3 R134.2
PHY1_LED1: length 35.5
  TOP w0.156: R137.1 94.32,74.79 v1(94.32,74.82) 93.64,75.5 U19.33
  TOP w0.203: J18.14 82.99,94.31 90.2,94.31 90.93,93.57 90.93,89.05 95.77,84.21 v1(95.77,82.68)
  BOTTOM w0.203: v1(95.77,82.68) 95.77,79.51 94.28,78.02 94.28,76.68 93.75,76.15 93.75,75.39 v1(94.32,74.82)
PHY1_LED2: length 26.4
  TOP w0.156: R138.1 94.34,75.8 94.34,75.82 v1(94.32,75.82) 94.24,75.9 U19.34
  TOP w0.203: v1(96.77,82.68) 96.77,83.92 91.47,89.23 91.47,95.46 J18.12
  BOTTOM w0.203: v1(96.77,82.68) 96.22,82.12 96.22,79.27 94.79,77.85 94.79,76.3 94.32,75.83 v1(94.32,75.82)
PWM3_IR: length 139.9
  TOP w0.156: J3.7 v1(33.78,64.94)
  ART03 w0.142: v1(145.54,95.83) 142.63,95.83 142.34,95.55 142.34,88.69 141.88,88.24 138.73,88.24 132.49,81.99 119.86,81.99 119.07,81.2 96.57,81.2 96.14,80.77 87.3,80.77 86.11,79.57 78.51,79.57 77.93,80.16 76.76,80.16 76.1,80.82 66.93,80.82 65.81,79.7 60.99,79.7 60.63,79.35 60.63,77.56 60.33,77.26 34.85,77.26 33.83,76.25 33.83,70.54 33.27,69.98 33.27,65.45 v1(33.78,64.94)
  BOTTOM w0.156: R34.1 v1(145.54,95.83)
RECOVERY_KEY: length 74.9
  TOP w0.156: J2.16 60.78,28.39 v1(61.28,28.89)
  ART03 w0.142: v1(13.69,25.87) 10.57,25.87 10.29,25.59 10.29,18.87 10.57,18.59 57.87,18.59 58.76,19.48 58.76,25.1 60.76,27.1 60.76,28.37 v1(61.28,28.89)
  BOTTOM w0.156: R26.2 14.78,25.55 14.46,25.87 v1(13.69,25.87)
REF_CLKN: length 14.6
  TOP w0.179: R111.2 143.07,82.27 143.07,83.02 v1(142.79,83.29)
  BOTTOM w0.179: R111.2 143.07,82.27 143.07,83.02 v1(142.79,83.29) 143.07,83.57 143.07,84.65 144.06,85.65 149.94,85.65 150.43,86.13 150.43,87.16 150.11,87.48 C127.1
REF_CLKP: length 14.6
  TOP w0.179: R87.2 143.45,82.27 143.45,83.02 v1(143.72,83.29)
  BOTTOM w0.179: C128.1 151.13,87.48 150.81,87.16 150.81,85.98 150.1,85.26 144.22,85.26 143.45,84.49 143.45,83.57 v1(143.72,83.29) 143.45,83.02 143.45,82.27 R87.2
REFCLKN: length 3.5
  TOP w0.179: v1(150.18,89.85) 149.71,90.32 149.71,90.91 149.65,90.97 J17.53
  BOTTOM w0.179: C127.2 150.43,89.26 150.43,89.6 v1(150.18,89.85)
REFCLKP: length 3.9
  TOP w0.179: J17.55 150.15,90.97 150.09,90.91 150.09,90.52 150.27,90.34 150.57,90.34 v1(151.07,89.85)
  BOTTOM w0.179: C128.2 150.81,89.26 150.81,89.6 v1(151.07,89.85)
RESET_KEY: length 55.1
  TOP w0.156: J1.29 39.28,24.39 38.78,24.89 v1(35.04,24.89)
  ART03 w0.142: v1(35.04,24.89) 34.56,24.41 34.56,19.2 34.27,18.92 10.98,18.92 10.69,19.2 10.69,22.69 v1(11.17,23.17)
  BOTTOM w0.156: v1(11.17,23.17) C63.1 9.83,22.54 9.83,20.2 D1.2 10.95,19.09 SW1.2
RS232_3V3: length 6
  TOP w0.381: L7.1 C42.1 v1(69.27,19.83)
  BOTTOM w0.381: U11.16 68,19.41 68.42,19.83 v1(69.27,19.83)
RS232_R1IN: length 6.7
  BOTTOM w0.254: J8.4 68.25,14.75 70.61,14.75 71.8,15.94 U11.13
RS232_R1OUT: length 22.5
  TOP w0.156: J13.1 81.11,6.78 80.52,7.37 80.52,15.19 80.09,15.62 73.43,15.62 73.08,15.97 73.08,18.33 v1(73.08,18.33)
  BOTTOM w0.156: U11.12 v1(73.08,18.33)
RS232_R2IN: length 14.5
  BOTTOM w0.254: U11.8 76.88,21.03 77.13,20.77 80.54,20.77 80.8,20.52 80.8,14.09 80.26,13.56 J8.1
RS232_R2OUT: length 14.7
  TOP w0.156: J14.1 84.4,13.84 84.4,17.36 84.09,17.67 77.19,17.67 76.88,17.99 v1(76.88,18.33)
  BOTTOM w0.156: U11.9 v1(76.88,18.33)
RS232_T1IN: length 19
  TOP w0.156: J13.2 81.67,9.32 81.36,9.63 81.36,15.99 81.04,16.3 74.5,16.3 74.34,16.46 v1(74.34,18.33)
  BOTTOM w0.156: U11.11 v1(74.34,18.33)
RS232_T1OUT: length 13.2
  BOTTOM w0.254: U11.14 70.54,15.69 70.29,15.44 61.32,15.44 J8.6
RS232_T2IN: length 11
  TOP w0.156: 83.31,15.29 81.64,16.96 75.92,16.96 75.62,17.26 v1(75.62,18.33)
  BOTTOM w0.156: U11.10 v1(75.62,18.33)
RS232_T2OUT: length 19.7
  BOTTOM w0.254: U11.7 75.62,19.83 75.97,19.48 79.1,19.48 79.53,19.05 79.53,15.72 79.12,15.31 72.62,15.31 J8.3
RS485_1_3V3: length 10.8
  TOP w0.305: v1(52.88,20.49) 52.15,19.76 50.68,19.76 49.92,19 C39.1
  TOP w0.381: L5.2 C39.1 v1(49.92,16.68)
  BOTTOM w0.305: D4.1 52.88,21.56 v1(52.88,20.49)
  BOTTOM w0.381: U8.8 50.03,16.79 v1(49.92,16.68)
RS485_1_A: length 21.2
  BOTTOM w0.254: U8.6 52.43,19.33 52.86,18.89 53.3,18.89 R38.2 ; R37.1 R38.2 ; R38.2 53.89,18.89 54.91,18.89 55.5,18.3 55.5,16.05 56.24,15.31 56.24,11.5 55.6,10.87 52.53,10.87 51.87,11.53 51.87,13.31 51.61,13.56 J10.2
RS485_1_B: length 19.4
  BOTTOM w0.254: R41.1 R38.1 ; R38.1 53.89,18.49 54.74,18.49 55.09,18.13 55.09,15.88 55.8,15.17 55.8,11.65 55.42,11.27 52.7,11.27 52.32,11.65 52.32,13.36 52.53,13.56 J10.1 ; R38.1 53.3,18.49 52.88,18.49 52.45,18.06 U8.7
RS485_1_DIR: length 97
  TOP w0.156: J4.41 v1(67.28,64.94)
  ART03 w0.142: v1(48.78,23.89) 49.29,23.39 50.98,23.39 51.41,23.82 51.41,30.76 52.66,32.01 65.6,32.01 68.76,28.85 73.74,28.85 v1(73.78,28.89)
  BOTTOM w0.156: v1(67.28,64.94) 67.28,61.79 65.23,59.74 62.92,59.74 61.67,58.49 61.67,51.41 62.38,50.69 73.46,50.69 73.78,50.37 v1(73.78,28.89) ; v1(48.78,23.89) 48.09,23.2 R40.1 48.36,22.01 48.36,19.86 47.83,19.33 U8.3 45.37,19.33 45.11,19.07 45.11,18.21 45.27,18.06 U8.2
RS485_2_3V3: length 13.8
  TOP w0.305: C44.1 39.38,19.68 v1(39.4,19.69)
  TOP w0.381: L6.2 C44.1 39.38,16.69 v1(39.37,16.68)
  ART04 w0.305: v1(39.4,19.69) 41.24,19.69 41.78,20.24 v1(41.78,23.89)
  BOTTOM w0.305: v1(41.78,23.89) 41.63,23.74 D5.1
  BOTTOM w0.381: v1(39.37,16.68) 39.47,16.79 U13.8
RS485_2_A: length 22.3
  BOTTOM w0.254: R67.1 R68.2 ; R68.2 43.38,18.87 43.83,18.87 44.42,18.27 44.42,16.13 44.93,15.62 47.52,15.62 48.44,14.7 48.44,12.51 48.44,12.17 47.74,11.48 44.91,11.48 44.42,11.96 44.42,13.38 44.24,13.56 J10.4 ; R68.2 42.76,18.89 42.29,18.89 41.86,19.33 U13.6
RS485_2_B: length 20
  BOTTOM w0.254: R68.1 43.31,18.45 43.67,18.45 44.02,18.11 44.02,15.92 44.73,15.21 47.35,15.21 48.03,14.52 48.03,12.34 47.57,11.88 45.09,11.88 44.83,12.14 44.83,13.33 45.06,13.56 J10.3 ; R68.1 R70.1 ; R68.1 42.76,18.49 42.39,18.49 41.96,18.06 U13.7
RS485_2_DIR: length 129.3
  TOP w0.156: v1(67.28,65.94) 67.78,65.44 J4.43
  ART03 w0.142: v1(37.78,23.89) 37.78,21.79 38.07,21.51 54.41,21.51 55.68,22.78 55.68,25.37 55.42,25.62 53.85,25.62 53.48,25.99 53.48,30.67 53.81,31 63.11,31 63.4,30.71 63.4,28.65 63.68,28.37 66.98,28.37 67.13,28.37 68.88,26.62 77.51,26.62 v1(77.78,26.89)
  BOTTOM w0.156: v1(67.28,65.94) 66.8,65.46 66.8,62.02 65,60.22 62.79,60.22 61.29,58.72 61.29,51.02 62.03,50.29 72.87,50.29 73.28,49.88 73.28,27.2 73.59,26.89 v1(77.78,26.89) ; v1(37.78,23.89) 37.55,23.66 R69.1 37.55,19.48 37.4,19.33 U13.3 34.57,19.33 34.37,19.12 34.37,18.28 34.59,18.06 U13.2
RX8010_NIRQ1: length 111.5
  TOP w0.156: v1(39.78,24.89) 40.28,24.39 J1.33
  ART03 w0.142: v1(39.78,24.89) 38.89,25.79 38.89,34.23 34.03,39.08 10.95,39.08 10.67,39.37 10.67,72.94 10.06,73.55 10.06,74.77 8.92,75.92 8.92,82.75 9.22,83.05 16.05,83.05 16.33,83.34 16.33,85.93 16.05,86.21 v1(11.76,86.21)
  BOTTOM w0.156: v1(11.76,86.21) 11.39,85.84 R72.2 10.79,87.16 11.11,87.47 16.32,87.47 16.64,87.16 U17.7
S0: length 2.4
  TOP w0.156: R86.2 140.59,78.52 U21.2
S1: length 2.3
  TOP w0.156: R85.2 140.23,77.87 U21.3
S2: length 2.1
  TOP w0.156: U21.4 139.86,77.22 R143.1
SARADC_VIN1: length 76.8
  TOP w0.156: R55.1 v1(115.14,24.81) ; v1(113.35,35.81) 111.39,37.77 63.02,37.77 61.85,36.6 61.85,28.7 61.28,28.13 J2.18
  BOTTOM w0.156: v1(115.14,24.81) 114.38,25.57 113.39,25.57 112.67,26.29 112.67,35.14 v1(113.35,35.81)
SARADC_VIN3: length 9.8
  TOP w0.156: R220.1 65.99,31.15 65.99,29.87 R219.2 v1(65.46,27.89) ; J2.20 v1(61.78,27.89)
  ART04 w0.142: v1(61.78,27.89) 62.3,27.38 64.95,27.38 v1(65.46,27.89)
SARADC_VIN4: length 73.4
  TOP w0.156: J2.22 62.28,36.22 63.37,37.31 110.85,37.31 v1(112.35,35.81) ; R56.1 v1(113.54,24.81)
  BOTTOM w0.156: v1(112.35,35.81) 112.06,35.53 112.06,26.29 v1(113.54,24.81)
SARADC_VIN5: length 70.8
  TOP w0.156: v1(111.35,35.81) 110.35,36.81 63.66,36.81 62.78,35.93 J2.24 ; R58.1 v1(111.94,24.81)
  BOTTOM w0.156: v1(111.35,35.81) 111.35,25.4 v1(111.94,24.81)
SARADC_VIN6: length 68.5
  TOP w0.156: R59.1 v1(110.34,24.81) ; v1(110.35,35.81) 109.86,36.29 63.93,36.29 63.28,35.65 J2.26
  BOTTOM w0.156: v1(110.34,24.81) 110.35,24.82 v1(110.35,35.81)
SARADC_VIN7: length 66.8
  TOP w0.156: v1(109.35,35.81) 64.1,35.81 63.78,35.5 J2.28 ; R71.1 v1(108.74,24.81)
  BOTTOM w0.156: v1(108.74,24.81) 109.35,25.42 v1(109.35,35.81)
SATA0_RXN: length 124.2
  TOP w0.124: v1(121.43,37.08) 121.73,37.38 121.73,40.92 121.48,41.17 52.03,41.17 49.2,38.34 49.2,27.72 49.28,27.63 J1.70
  BOTTOM w0.124: C62.1 125.63,11.86 125.63,13.79 125.35,14.07 124.67,14.07 arc(124.59,14.03) 124.56,13.95 arc(124.52,13.87) 124.44,13.84 124.17,13.84 arc(124.09,13.87) 124.06,13.95 arc(124.03,14.03) 123.95,14.07 123.68,14.07 arc(123.6,14.03) 123.56,13.95 arc(123.53,13.87) 123.45,13.84 123.18,13.84 arc(123.1,13.87) 123.07,13.95 arc(123.03,14.03) 122.95,14.07 122.69,14.07 arc(122.61,14.03) 122.57,13.95 arc(122.54,13.87) 122.46,13.84 122.19,13.84 arc(122.11,13.87) 122.08,13.95 arc(122.04,14.03) 121.96,14.07 121.69,14.07 arc(121.61,14.03) 121.58,13.95 arc(121.55,13.87) 121.47,13.84 121.2,13.84 arc(121.12,13.87) 121.08,13.95 arc(121.05,14.03) 120.97,14.07 119.28,14.07 118.84,14.51 118.84,20.61 119.39,21.17 119.39,26.64 121.73,28.98 121.73,36.78 v1(121.43,37.08)
SATA0_RXP: length 124.2
  TOP w0.124: J1.68 48.78,27.63 48.87,27.72 48.87,38.48 51.89,41.5 121.61,41.5 122.05,41.06 122.05,37.38 v1(122.35,37.08)
  BOTTOM w0.124: v1(122.35,37.08) 122.06,36.78 122.06,28.84 119.72,26.51 119.72,21.03 119.17,20.48 119.17,14.64 119.41,14.39 125.48,14.39 125.96,13.92 125.96,11.83 C211.1
SATA0_TXN: length 123.9
  TOP w0.124: J1.74 50.28,27.63 50.2,27.72 50.2,37.93 52.55,40.28 118.66,40.28 118.91,40.03 118.91,37.35 v1(118.61,37.05)
  BOTTOM w0.124: C61.1 122.17,11.83 122.17,12.85 121.72,13.31 118.16,13.31 117.88,13.59 117.88,20.87 118.56,21.55 118.56,27.32 120.62,29.38 120.62,33.13 120.28,33.47 119.24,33.47 119.1,33.61 119.1,33.82 119.24,33.96 120.28,33.96 120.62,34.3 120.62,34.78 120.28,35.12 119.24,35.12 119.1,35.26 119.1,35.47 119.24,35.61 120.28,35.61 120.62,35.95 120.62,37.88 120.25,38.25 119.23,38.25 118.91,37.93 118.91,37.35 v1(118.61,37.05)
SATA0_TXP: length 123.9
  TOP w0.124: v1(119.54,37.05) 119.24,37.35 119.24,40.17 118.8,40.61 52.42,40.61 49.87,38.06 49.87,27.72 49.78,27.63 J1.72
  BOTTOM w0.124: C60.1 121.84,11.85 121.84,12.72 121.58,12.98 118.03,12.98 117.55,13.45 117.55,21.01 118.24,21.69 118.24,27.45 120.29,29.51 120.29,33 120.15,33.14 119.11,33.14 118.77,33.48 118.77,33.96 119.11,34.29 120.15,34.29 120.29,34.44 120.29,34.64 120.15,34.79 119.11,34.79 118.77,35.12 118.77,35.6 119.11,35.94 120.15,35.94 120.29,36.08 120.29,37.74 120.12,37.92 119.36,37.92 119.24,37.79 119.24,37.35 v1(119.54,37.05)
SATA0RXN: length 3.8
  BOTTOM w0.124: J34.5 125.62,7.92 125.62,10.6 C62.2
SATA0RXP: length 3.8
  BOTTOM w0.124: C211.2 125.95,10.61 125.95,7.92 J34.6
SATA0TXN: length 3.8
  BOTTOM w0.124: C61.2 122.14,10.58 122.14,7.92 J34.3
SATA0TXP: length 3.8
  BOTTOM w0.124: J34.2 121.81,7.92 121.81,10.62 C60.2
SATA_5V: length 6.2
  TOP w0.305: v1(121.44,18.16) 118.92,18.16 118.62,18.46 R201.2 C206.2
  BOTTOM w0.305: v1(124.33,20.95) 124.18,21.1 124.18,21.28 124.07,21.39 C208.1
  vias: v1(124.33,19.95) v1(125.33,20.95) v1(125.33,19.95)
SATA_12V: length 4.8
  TOP w0.305: C59.1 v1(135.76,16.3)
  BOTTOM w0.508: 129.22,15.1 J40.4 ; J40.4 128.32,16 ; J40.4 129.22,16.9 ; J40.4 130.12,16
  vias: v1(136.76,16.3) v1(136.76,15.3)
SATA_PWR_EN: length 92.6
  TOP w0.156: J2.74 75.28,30.8 75.6,31.11 121.77,31.11 v1(123.72,29.16) ; v1(132.68,6.27) 132.11,6.27 131.9,6.48 131.9,17.88 130.81,18.97 122.06,18.97 v1(121.41,19.61) R209.2
  BOTTOM w0.156: v1(123.72,29.16) 120.47,25.9 120.47,20.61 120.44,20.58 v1(121.41,19.61) ; v1(132.68,6.27) 133.26,6.85 134.92,6.85 R206.1
SDMMC0_CLK: length 103.4
  TOP w0.156: J2.13 60.28,24.39 v1(60.78,24.89)
  ART03 w0.142: v1(60.78,24.89) 60.78,24.64 60.31,24.16 60.31,22.24 60.88,21.66 60.88,17.53 61.19,17.22 64.03,17.22 64.87,16.38 64.94,16.38 64.96,16.36 118.53,16.36 118.87,16.02 118.87,14.8 119.35,14.32 138.82,14.32 139.26,14.76 139.26,16.65 139.9,17.29 139.9,24.48 139.39,25 v1(138.48,25)
  BOTTOM w0.156: R54.1 v1(138.48,25)
SDMMC0_CMD: length 103.2
  TOP w0.156: J2.15 v1(60.78,23.89)
  ART03 w0.142: v1(138.48,22.41) 139.03,22.41 139.45,22 139.45,17.67 138.25,16.48 138.25,15.09 137.92,14.75 119.74,14.75 119.33,15.16 119.33,16.43 118.95,16.81 94.51,16.81 94.35,16.98 94.35,18.04 94.18,18.21 93.94,18.21 93.78,18.04 93.78,16.98 93.61,16.81 93.37,16.81 93.21,16.98 93.21,18.04 93.04,18.21 92.8,18.21 92.64,18.04 92.64,16.98 92.47,16.81 92.23,16.81 92.07,16.98 92.07,18.04 91.9,18.21 91.66,18.21 91.5,18.04 91.5,16.98 91.33,16.81 65.05,16.81 64.21,17.65 61.64,17.65 61.35,17.93 61.35,21.88 60.78,22.45 v1(60.78,23.89)
  BOTTOM w0.156: R53.1 v1(138.48,22.41)
SDMMC0_D0: length 102.7
  TOP w0.156: J2.19 v1(61.78,23.89)
  ART03 w0.142: v1(61.78,23.89) 61.78,22.29 62.48,21.59 62.48,18.34 62.72,18.11 64.41,18.11 65.28,17.24 88.46,17.24 88.62,17.41 88.62,18.5 88.79,18.67 89.03,18.67 89.19,18.5 89.19,17.41 89.36,17.24 89.6,17.24 89.76,17.41 89.76,18.5 89.93,18.67 90.17,18.67 90.33,18.5 90.33,17.41 90.5,17.24 90.74,17.24 90.9,17.41 90.9,18.5 91.07,18.67 94.89,18.67 96.32,17.24 138.4,17.24 139.01,17.85 139.01,21.58 138.73,21.87 137.88,21.87 137.69,22.05 137.69,26.63 137.88,26.81 v1(138.48,26.81)
  BOTTOM w0.156: R57.1 v1(138.48,26.81)
SDMMC0_D1: length 103.4
  TOP w0.156: J2.21 62.28,24.39 v1(62.78,24.89)
  ART03 w0.142: v1(138.48,27.92) 137.44,27.92 137.26,27.73 137.26,18.89 136.93,18.56 122.86,18.56 122.3,19.12 120.35,19.12 120.02,19.45 115.98,19.45 115.11,18.59 97.08,18.59 95.66,20.01 82.36,20.01 82.22,19.87 82.22,18.78 82.05,18.61 81.81,18.61 81.65,18.78 81.65,19.84 81.48,20.01 81.24,20.01 81.08,19.84 81.08,18.78 80.91,18.61 80.67,18.61 80.51,18.78 80.51,19.84 80.34,20.01 80.1,20.01 79.94,19.84 79.94,18.76 79.79,18.61 79.52,18.61 79.36,18.78 79.36,19.84 79.19,20.01 78.95,20.01 78.79,19.84 78.79,19.59 78.62,19.43 78.38,19.43 78.22,19.59 78.22,19.84 78.05,20.01 77.81,20.01 77.65,19.84 77.65,19.59 77.48,19.43 76.12,19.43 75.9,19.66 75.9,21.36 75.64,21.61 64.59,21.61 64.31,21.9 64.31,25.08 64.02,25.37 63.26,25.37 v1(62.78,24.89)
  BOTTOM w0.156: R60.1 v1(138.48,27.92)
SDMMC0_D2: length 101.3
  TOP w0.156: J2.23 v1(62.78,23.89)
  ART03 w0.142: v1(138.48,20.22) 138.48,18.06 138.1,17.67 96.52,17.67 95.1,19.1 88.2,19.1 88.03,18.93 88.03,17.92 87.86,17.75 87.63,17.75 87.46,17.92 87.46,18.93 87.29,19.1 87.06,19.1 86.89,18.93 86.89,17.92 86.72,17.75 86.49,17.75 86.32,17.92 86.32,18.93 86.15,19.1 85.92,19.1 85.75,18.93 85.75,17.92 85.58,17.75 85.35,17.75 85.18,17.92 85.18,18.93 85.01,19.1 84.78,19.1 84.61,18.93 84.61,17.92 84.44,17.75 84.21,17.75 84.04,17.92 84.04,18.93 83.87,19.1 83.64,19.1 83.47,18.93 83.47,17.92 83.3,17.75 71.94,17.75 71.77,17.92 71.77,18.35 71.6,18.52 71.37,18.52 71.2,18.35 71.2,17.92 71.03,17.75 70.8,17.75 70.63,17.92 70.63,18.35 70.46,18.52 70.23,18.52 70.06,18.35 70.06,17.92 69.89,17.75 68.69,17.75 68.52,17.92 68.52,18.42 68.35,18.59 68.12,18.59 67.95,18.42 67.95,17.92 67.78,17.75 67.55,17.75 67.38,17.92 67.38,18.42 67.21,18.59 66.94,18.59 66.78,18.42 66.78,17.92 66.61,17.75 66.37,17.75 66.21,17.92 66.21,18.42 66.04,18.59 63.78,18.59 63.45,18.92 63.45,21.38 62.78,22.05 v1(62.78,23.89)
  BOTTOM w0.156: R51.1 v1(138.48,20.22)
SDMMC0_D3: length 105.8
  TOP w0.156: J2.25 63.28,24.39 v1(63.78,24.89)
  ART03 w0.142: v1(138.48,21.32) 138.13,21.32 137.85,21.03 137.85,18.39 137.59,18.13 122.56,18.13 122.02,18.67 120.45,18.67 119.91,18.13 96.88,18.13 95.45,19.55 83.06,19.55 82.89,19.39 82.89,18.33 82.75,18.18 79.25,18.18 78.49,18.94 73.26,18.94 73.09,19.11 73.09,19.72 72.92,19.88 72.69,19.88 72.52,19.72 72.52,19.11 72.35,18.94 72.12,18.94 71.95,19.11 71.95,19.72 71.78,19.88 71.55,19.88 71.38,19.72 71.38,19.11 71.21,18.94 70.98,18.94 70.81,19.11 70.81,19.72 70.64,19.88 70.41,19.88 70.24,19.72 70.24,19.11 70.07,18.94 68.92,18.94 68.63,19.24 68.63,20.28 68.46,20.44 68.23,20.44 68.06,20.28 68.06,19.24 67.89,19.07 67.66,19.07 67.49,19.24 67.49,20.28 67.32,20.44 67.09,20.44 66.92,20.28 66.92,19.24 66.75,19.07 66.52,19.07 66.32,19.26 66.32,20.89 66.16,21.05 65.92,21.05 65.75,20.89 65.75,19.21 65.61,19.07 65.38,19.07 65.18,19.26 65.18,20.89 65.02,21.05 64.78,21.05 64.61,20.89 64.61,19.21 64.47,19.07 64.16,19.07 63.91,19.33 63.91,21.56 63.3,22.17 63.3,24.4 v1(63.78,24.89)
  BOTTOM w0.156: R52.1 v1(138.48,21.32)
SDMMC0_DET: length 106
  TOP w0.156: J2.17 61.28,24.39 v1(61.78,24.89)
  ART03 w0.142: v1(61.78,24.89) 62.7,25.8 64.84,25.8 65.26,25.38 65.26,22.21 65.43,22.04 66.18,22.04 66.35,22.21 66.35,22.61 66.51,22.78 66.75,22.78 66.92,22.61 66.92,22.21 67.08,22.04 67.32,22.04 67.49,22.21 67.49,22.61 67.65,22.78 67.89,22.78 68.06,22.61 68.06,22.21 68.22,22.04 68.46,22.04 68.63,22.21 68.63,22.61 68.79,22.78 69.03,22.78 69.19,22.61 69.19,22.21 69.36,22.04 69.6,22.04 69.76,22.21 69.76,22.61 69.93,22.78 70.17,22.78 70.33,22.61 70.33,22.21 70.5,22.04 70.74,22.04 70.9,22.21 70.9,22.61 71.07,22.78 71.31,22.78 71.47,22.61 71.47,22.21 71.64,22.04 71.88,22.04 72.04,22.21 72.04,22.61 72.21,22.78 72.45,22.78 72.61,22.61 72.61,22.21 72.78,22.04 73.02,22.04 73.18,22.21 73.18,22.61 73.35,22.78 73.59,22.78 73.75,22.61 73.75,22.21 73.92,22.04 74.16,22.04 74.32,22.21 74.32,22.61 74.49,22.78 74.73,22.78 74.89,22.61 74.89,22.21 75.06,22.04 75.3,22.04 75.46,22.21 75.46,22.61 75.63,22.78 76.2,22.78 76.39,22.59 76.39,20.73 76.68,20.44 95.96,20.44 97.36,19.05 114.8,19.05 115.87,20.11 122.76,20.11 123.85,19.02 132.28,19.02 133.07,19.81 136.55,19.81 136.8,20.06 136.8,28.85 136.99,29.03 138.47,29.03 v1(138.48,29.02)
  BOTTOM w0.156: R61.1 v1(138.48,29.02)
SIM_CLK0: length 46.6
  TOP w0.156: J35.12 v1(124.3,66.68)
  BOTTOM w0.156: v1(124.3,66.68) 124.06,66.68 123.24,65.86 120.8,65.86 120.62,65.68 120.62,45.87 122.05,44.45 134.87,44.45 135.18,44.13 135.18,40.11 135.49,39.8 R20.1
SIM_DATA0: length 65.3
  TOP w0.156: J35.10 125.1,66.48 v1(124.3,65.68)
  BOTTOM w0.156: v1(124.3,65.68) 124.76,65.68 125.09,66.01 125.09,67.23 124.54,67.79 119.91,67.79 119.2,67.08 119.2,57.68 119.05,57.53 118.21,57.53 117.81,57.12 117.81,39.15 118.12,38.83 129.95,38.83 130.35,38.43 130.35,35.91 130.76,35.51 138.46,35.51 R21.1
SIM_RST0: length 50.2
  TOP w0.156: v1(122.92,66.68) 123.17,66.68 123.5,67.01 J35.14
  BOTTOM w0.156: R19.1 134.7,37.26 134.39,37.57 134.39,43.19 134.08,43.51 121.84,43.51 119.05,46.3 119.05,54.86 119.96,55.77 119.96,66.04 120.61,66.68 v1(122.92,66.68)
SIM_VDD: length 69.9
  TOP w0.381: v1(126.3,66.68) 125.9,67.08 J35.8
  ART03 w0.381: v1(140.2,40.32) 140.2,37.71 139.75,37.26 v1(138.52,37.26)
  ART04 w0.381: v1(126.3,66.68) 125.34,67.64 119.53,67.64 118.82,66.93 118.82,60.3 117.81,59.28 117.81,55.11 118.87,54.05 v1(118.87,45.36)
  BOTTOM w0.305: U15.6 v1(140.2,40.32) ; R18.1 v1(138.52,37.26)
  BOTTOM w0.381: v1(138.52,37.26) 138.52,36.48 138.07,36.04 133.81,36.04 133.35,36.5 133.35,41.73 132.59,42.49 119.58,42.49 118.87,43.2 v1(118.87,45.36) ; v1(140.2,40.32) 140.2,40.31 U14.1
SPKN_OUT: length 67.8
  TOP w0.203: J1.24 37.78,27.62 37.69,27.71 37.69,43.84 36.91,44.62 35.98,44.62 25.6,44.62 25.2,45.03 25.2,55.83 25.6,56.23 27.69,56.23 28.1,55.83 28.1,55.22 v1(27.82,54.94)
  BOTTOM w0.203: v1(27.82,54.94) 28.12,55.24 28.12,56.79 30.1,58.77 30.1,69.36 30.91,70.18 33.96,70.18 34.52,70.74 34.52,72.22 R218.1
SPKP_OUT: length 68.9
  TOP w0.203: J1.22 37.28,27.6 37.34,27.66 37.34,43.69 36.76,44.27 25.46,44.27 25.45,44.28 24.84,44.88 24.84,55.97 25.46,56.59 27.84,56.59 28.45,55.97 28.45,55.23 v1(28.75,54.94)
  BOTTOM w0.203: v1(28.75,54.94) 28.47,55.21 28.47,56.64 30.45,58.62 30.45,69.22 31.06,69.82 34.11,69.82 34.87,70.59 34.87,72.27 R217.1
U7_RX: length 7.6
  TOP w0.156: J9.3 94.25,7.12 93.9,6.78 J13.5
U7_TX: length 9.5
  TOP w0.156: J13.6 89.23,10.16 95.94,10.16 96.25,9.84 J9.2
U9_RX: length 7.6
  TOP w0.156: J12.3 94.26,14.61 94.26,13.06 93.95,12.75 J14.5
U9_TX: length 9.3
  TOP w0.156: 88.39,15.29 89.08,15.97 95.89,15.97 96.25,15.61 J12.2
UART2_RX: length 13.7
  TOP w0.156: U12.2 2.42,21.07 2.94,20.55 8.58,20.55 8.76,20.37 v1(8.76,19.6)
  BOTTOM w0.156: R36.2 v1(8.76,19.6)
UART2_RX_M0_DEBUG: length 71.6
  TOP w0.156: v1(36.78,56.94) 37.28,57.44 J3.22 ; U12.4 v1(1.77,23.05)
  BOTTOM w0.156: v1(36.78,56.94) 35.82,56.94 35.51,56.62 35.51,36.99 35.2,36.67 8.97,36.67 8.18,35.89 8.18,26.17 7.87,25.85 2.21,25.85 1.77,25.41 v1(1.77,23.05)
UART2_TX: length 6
  TOP w0.156: v1(8.76,22.27) 6.12,22.27 5.96,22.43 U4.4
  BOTTOM w0.156: v1(8.76,22.27) R23.2
UART2_TX_M0_DEBUG: length 62
  TOP w0.156: U4.2 6.61,27.58 v1(7.26,28.23) ; J3.20 v1(36.78,57.94)
  BOTTOM w0.156: v1(36.78,57.94) 35.16,57.94 34.85,57.62 34.85,37.65 34.54,37.33 8.65,37.33 7.27,35.95 7.27,28.24 v1(7.26,28.23)
UART3_RX_M1: length 61.8
  TOP w0.156: J4.13 v1(60.28,64.94)
  ART04 w0.142: v1(60.28,64.94) 60.28,33.73 58.47,31.91 58.47,29.38 58.09,29 49.59,29 49.3,28.71 49.3,23.52 49.14,23.35 v1(49.14,20.49)
  BOTTOM w0.156: U8.1 48.69,16.79 49.14,17.23 v1(49.14,20.49)
UART3_TX_M1: length 59.2
  TOP w0.156: v1(59.28,65.94) 59.78,65.44 J4.11
  ART04 w0.142: v1(47.57,20.49) 47.57,22.93 48.29,23.64 48.29,29.71 48.57,29.99 56.26,29.99 56.52,30.25 56.52,32.48 57.89,33.85 57.89,60.42 59.76,62.3 59.76,65.46 v1(59.28,65.94)
  BOTTOM w0.156: U8.4 47.47,20.6 v1(47.57,20.49)
